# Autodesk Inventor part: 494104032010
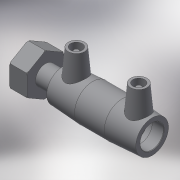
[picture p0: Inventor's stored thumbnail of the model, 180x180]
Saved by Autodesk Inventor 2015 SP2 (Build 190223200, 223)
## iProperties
Created: 2017-06
Part Number: 494104032010
Material: Generic
Description: PLASSON FEMALE FREE NUT TRANSITION COUPLER 32-3/4"
Document SubType Name: Modeling
Designer: KIM
Mass: 55.0731 g
Surface Area: 148.067 cm^2
Volume: 55.0731 cm^3
Density: 1 g/cm^3
Appearance: Default
Author: KIM
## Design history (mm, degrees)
derived "494104.ipt"
feature "Solid1::494104.ipt"
tag "TaggingFeature1"
body "Solid1"
other parameters: "d0" = 88, "d1" = 32, "d2" = 44, "d3" = 42, "d4" = 29.33333, "d5" = 39.6, "d6" = 30.4, "d7" = 32, "d8" = 168 deg, "d10" = 16.8, "d11" = 5.6, "d29" = 42, "d30" = 14, "d31" = 30.8, "d34" = 5 deg, "d41" = 4, "d42" = 14, "d43" = 0, "d48" = 3, "d49" = 0, "d55" = 36, "d57" = 19, "d80" = 0.64, "d83" = 18, "d84" = 11.88, "d85" = 1.188, "d86" = 24.2328, "d87" = 30.291, "d88" = 45.4365, "d89" = 44, "d90" = 0.90873, "d94" = 0, "d95" = 1.188, "d96" = 21.2037, "d_" = 32, "L_" = 124, "L_1" = 42, "D_1" = 44, "A_" = 42, "d_2" = 12, "L_2" = 36, "D_" = 19, "G_" = 30.291
